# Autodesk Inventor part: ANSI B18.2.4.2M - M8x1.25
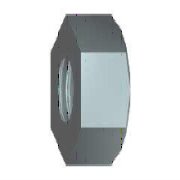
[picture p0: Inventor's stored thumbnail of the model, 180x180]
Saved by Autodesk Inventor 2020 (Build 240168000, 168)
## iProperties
Created: 2008-02
Part Number: ANSI B18.2.4.2M - M8x1.25
Material: Steel, Mild
Description: Metric Hex Nuts
Document SubType Name: Modeling
Standard: ANSI B18.2.4.2M
Designer: PN
Standards Organization: ANSI
Language: en-US
Size Designation: M8x1.25
Categories: <MemberInstance><Categories><Category DisplayName="Fasteners" InternalName="e4da775c-781d-43d5-af7c-5136215cf5a6" Mnemonic="FSTN"><Category DisplayName="Nuts" I
Density: 7.86 g/cm^3
Mass: 6.47658 g
Surface Area: 6.89688 cm^2
Volume: 0.823992 cm^3
Appearance: Steel
IsCustomPart: 0
Author: PN
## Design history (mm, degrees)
sketch "Sketch1"
  geometry: L1 (6.5, 3.753)-(6.5, -3.753); L2 (6.5, -3.753)-(0, -7.506); L3 (0, -7.506)-(-6.5, -3.753); L4 (-6.5, -3.753)-(-6.5, 3.753); L5 (-6.5, 3.753)-(0, 7.506); L6 (0, 7.506)-(6.5, 3.753); C1 r 6.5 at (0, 0); 2 further points
  constraints: 12 end point, 2 coincident, 1 centre point, 1 tangent, 1 vertical, 11 other
  dimensions: "d0" = 13 diameter of C1 (= Smax)
extrude "Extrusion1" new body sketch "Sketch1" distance "d1" = 7.5 (= Mmax); taper "d2" = 0 deg
chamfer "Chamfer1" distance "d10" = 0.625 (= 0.5 x PTC); stored, may be unused: second distance "d11" = 2, angle "d12" = 45 deg
sketch "Sketch3"
  geometry: L1 (-9.171, 0)-(2.529, 0) reference; L2 (-5.705, 0)-(0.857, 0); L3 (-7.5, 0)-(-7.5, -7.506); L4 (-7.5, -7.506)-(0, -7.506); L5 (0, -7.506)-(0, 0); L6 (-7.5, -3.753)-(-7.5, -7.506) reference; L7 (0, -3.753)-(0, -7.506) reference; L8 (0, -7.506)-(-7.5, -7.506) reference; L9 (-7.5, -6.5)-(-6.919, -7.506); L10 (-7.5, -7.506)-(-7.5, -6.5); L11 (-7.5, -7.506)-(-6.919, -7.506); L12 (0, -6.5)-(-0.581, -7.506); L13 (-0.581, -7.506)-(0, -7.506); L14 (0, -7.506)-(0, -6.5)
  constraints: 21 end point, 6 point on line, 5 collinear, 4 vertical, 3 equal length, 2 horizontal
  dimensions: "d32" = 6.5 distance from line of L9.start L1 (= 0.5 x Smax); "d33" = 30 deg angle of L9 L3
revolve "Revolution1" sketch "Sketch3" stored, may be unused: angle "d15" = 90 deg
node "MSC_A1"
node "MSC_PT1"
node "MSC_PT2"
node "MSC_PF1"
body "Solid1"
sketch "Sketch2"
  geometry: L1 (-6.5, 3.753)-(0, 7.506) reference; L2 (0, -7.506)-(-6.5, -3.753) reference; L3 (-6.5, 3.753)-(6.5, -3.753); L4 (-6.5, -3.753)-(6.5, 3.753); 1 further point
  constraints: 4 end point, 2 midpoint, 2 parallel
hole "Hole1" sketch "Sketch2" diameter "d3" = 6.647; stored, may be unused: countersink angle "d7" = 90 deg, drill point angle "d9" = 118 deg; dims "d4" = 6, "d5" = 4, "d6" = 2, "d8" = 8
other parameters: "NND" = 8 [user parameter; used in 1 equation term], "Smax" = 13 [user parameter; used in 2 equation terms], "Mmax" = 7.5 [user parameter; used in 1 equation term], "PTC" = 1.25 [user parameter; used in 1 equation term], "d16" = 0, "d17" = 0, "d18" = 0, "d19" = 0, "d21" = 0, "d22" = 0, "d23" = 0, "THREADDIA" = 8 (= NND) [user parameter], "TEMPLATE" = 12.345 [user parameter]
